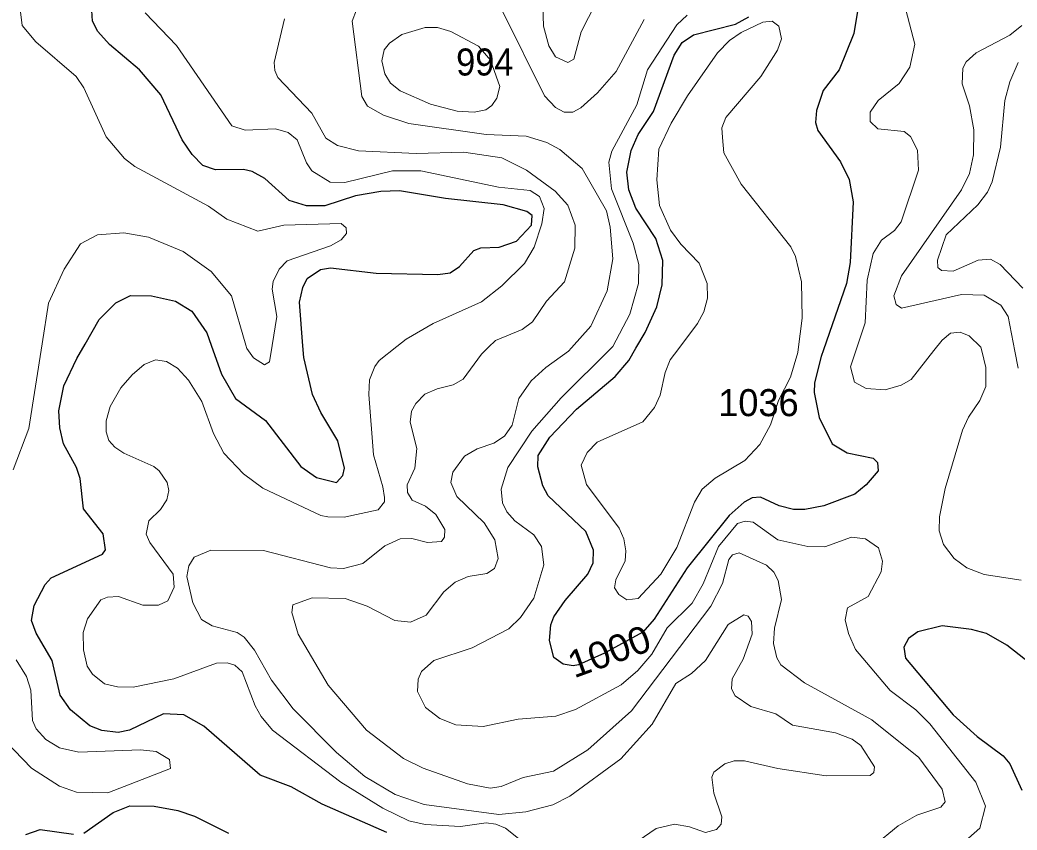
# Model space of a CAD drawing. Extents: x 473.9 to 500, y 7733.1 to 7760.8.
# Drawn here: x 479.198 to 482.147, y 7746.544 to 7748.942 of the extents above; entities that cross this region are included whole.
import ezdxf
from ezdxf.enums import TextEntityAlignment as Align

# ---------------------------------------------------------------- set-up
doc = ezdxf.new("R2010")
doc.units = 0
doc.header["$LTSCALE"] = 0.032
doc.layers.add('1', color=7, linetype='Continuous', lineweight=25)
doc.layers.add('2', color=7, linetype='Continuous', lineweight=13)
doc.layers.add('21', color=7, linetype='Continuous')
doc.layers.add('61', color=7, linetype='Continuous')

msp = doc.modelspace()

# ---------------------------------------------------------------- linework, layer by layer
at = {"layer": '1'}
for points in [[(481.6787, 7748.9918), (481.664, 7748.9011), (481.621, 7748.794), (481.5738, 7748.7331), (481.554, 7748.6734), (481.5507, 7748.6378), (481.5572, 7748.6146), (481.6246, 7748.5216), (481.6499, 7748.4698), (481.6616, 7748.4036), (481.6535, 7748.2242), (481.6423, 7748.1614), (481.5745, 7747.9657), (481.5675, 7747.9454), (481.5479, 7747.8675), (481.5467, 7747.8395), (481.5618, 7747.7649), (481.6003, 7747.6876), (481.6439, 7747.6606), (481.7211, 7747.6443), (481.7341, 7747.6319), (481.7364, 7747.6076), (481.7009, 7747.5655), (481.667, 7747.5385), (481.5754, 7747.5038), (481.5196, 7747.4928), (481.486, 7747.4932), (481.4435, 7747.5036), (481.3876, 7747.5295), (481.3631, 7747.5271), (481.3393, 7747.5142), (481.295, 7747.4749), (481.1707, 7747.3206), (481.0738, 7747.168), (481.0404, 7747.1294), (480.9267, 7747.068), (480.8499, 7747.0326), (480.834, 7747.0303), (480.8044, 7747.035), (480.7766, 7747.0543), (480.7643, 7747.1048), (480.7683, 7747.151), (480.7763, 7747.1747), (480.8099, 7747.223), (480.8775, 7747.3018), (480.8928, 7747.335), (480.8938, 7747.3723), (480.8715, 7747.4277), (480.7605, 7747.5337), (480.7443, 7747.5626), (480.729, 7747.6192), (480.7306, 7747.6521), (480.7646, 7747.707), (480.8441, 7747.7896), (480.9585, 7747.8868), (480.9983, 7747.9342), (481.0196, 7747.9699), (481.0471, 7748.0162), (481.0811, 7748.0924), (481.0972, 7748.1572), (481.0988, 7748.23), (481.0787, 7748.2949), (481.0195, 7748.3847), (480.9988, 7748.4392), (480.9927, 7748.4907), (481.0053, 7748.5552), (481.0263, 7748.6031), (481.0717, 7748.671), (481.1323, 7748.8379), (481.1566, 7748.8745), (481.1894, 7748.8973), (481.3141, 7748.9296), (481.3534, 7748.9505)], [(479.6826, 7746.8849), (479.6222, 7746.8877), (479.5219, 7746.8399), (479.4885, 7746.8325), (479.44, 7746.8387), (479.4041, 7746.8529), (479.347, 7746.8997), (479.3171, 7746.9429), (479.2926, 7747.0459), (479.2458, 7747.1271), (479.232, 7747.1645), (479.2402, 7747.2088), (479.2721, 7747.2706), (479.2903, 7747.2905), (479.4417, 7747.3603), (479.4505, 7747.3731), (479.4435, 7747.421), (479.3861, 7747.4948), (479.376, 7747.5847), (479.3655, 7747.6173), (479.3261, 7747.6875), (479.3155, 7747.7344), (479.3123, 7747.7852), (479.3278, 7747.859), (479.3662, 7747.9398), (479.3908, 7747.9824), (479.4325, 7748.0548), (479.4811, 7748.1042), (479.5243, 7748.126), (479.5872, 7748.1252), (479.6574, 7748.1093), (479.706, 7748.0793), (479.7509, 7748.0159), (479.7636, 7747.9796), (479.7939, 7747.893), (479.8353, 7747.8217), (479.9236, 7747.7558), (480.0283, 7747.6204), (480.0751, 7747.5879), (480.1338, 7747.5722), (480.1523, 7747.5938), (480.1579, 7747.615), (480.1381, 7747.6956), (480.0877, 7747.7799), (480.0632, 7747.8329), (480.0374, 7747.9425), (480.0347, 7747.9775), (480.0247, 7748.1068), (480.0343, 7748.15), (480.0476, 7748.1769), (480.0869, 7748.2029), (480.1163, 7748.208), (480.2512, 7748.1924), (480.4336, 7748.1887), (480.4697, 7748.1936), (480.4978, 7748.2118), (480.5399, 7748.2589), (480.561, 7748.2675), (480.6154, 7748.2688), (480.6659, 7748.2865), (480.7103, 7748.334), (480.7123, 7748.3631), (480.6969, 7748.3747), (480.627, 7748.3943), (480.4559, 7748.4131), (480.3199, 7748.4357), (480.2649, 7748.4341), (480.1899, 7748.4206), (480.0996, 7748.3914), (480.045, 7748.3918), (479.9942, 7748.4075), (479.9223, 7748.4722), (479.8849, 7748.4929), (479.859, 7748.4993), (479.776, 7748.4982), (479.7391, 7748.511), (479.7069, 7748.5438), (479.6779, 7748.5869), (479.6141, 7748.7205), (479.5513, 7748.7939), (479.4623, 7748.8694), (479.4277, 7748.9071), (479.4122, 7748.9377), (479.4104, 7748.9696)], [(482.2035, 7747.0234), (482.117, 7747.0917), (482.0562, 7747.1256), (482.0122, 7747.1379), (481.9253, 7747.1483), (481.8531, 7747.1307), (481.8253, 7747.1105), (481.8115, 7747.085), (481.8168, 7747.0528), (481.958, 7746.8851), (482.0288, 7746.8212), (482.106, 7746.7633), (482.1257, 7746.7401), (482.1612, 7746.6623)], [(480.283, 7746.5365), (480.0912, 7746.6207), (480.0003, 7746.6718), (479.9087, 7746.7065), (479.742, 7746.8516), (479.6826, 7746.8849)], [(479.3865, 7746.5349), (479.4739, 7746.596), (479.523, 7746.6153), (479.5944, 7746.6145), (479.6644, 7746.6024), (479.7143, 7746.5855), (479.8146, 7746.5346)], [(479.215, 7746.5311), (479.2577, 7746.546), (479.356, 7746.5314)]]:
    msp.add_lwpolyline(points, dxfattribs=at)
at = {"layer": '2'}
for points in [[(479.9571, 7748.0638), (479.9435, 7748.1448), (479.9467, 7748.1679), (479.9649, 7748.2041), (479.9882, 7748.2284), (480.1167, 7748.2735), (480.1482, 7748.291), (480.1636, 7748.31), (480.1626, 7748.3261), (480.1475, 7748.339), (479.978, 7748.3343), (479.9016, 7748.3167), (479.8101, 7748.3523), (479.7555, 7748.3907), (479.5377, 7748.5084), (479.5072, 7748.5318), (479.4524, 7748.596), (479.387, 7748.7403), (479.3641, 7748.7744), (479.2451, 7748.8766), (479.2046, 7748.9254), (479.1918, 7749.0303), (479.1979, 7749.1483), (479.166, 7749.3096)], [(480.7431, 7749.0143), (480.746, 7748.9231), (480.7618, 7748.8648), (480.7813, 7748.8323), (480.8185, 7748.8153), (480.8361, 7748.8258), (480.858, 7748.9066), (480.9661, 7749.1191)], [(479.568, 7748.9631), (479.6605, 7748.8659), (479.8245, 7748.6287), (479.8639, 7748.6158), (479.9532, 7748.619), (479.991, 7748.6086), (480.0175, 7748.5869), (480.0448, 7748.5185), (480.0609, 7748.4952), (480.1148, 7748.4614), (480.1582, 7748.4606), (480.2997, 7748.4952), (480.3833, 7748.4952), (480.6133, 7748.447), (480.7065, 7748.4373), (480.7339, 7748.4196), (480.7483, 7748.3834), (480.7411, 7748.3384), (480.7186, 7748.2693), (480.6904, 7748.221), (480.6229, 7748.1551), (480.5626, 7748.1077), (480.4203, 7748.0433), (480.3399, 7747.9967), (480.3128, 7747.9754), (480.2603, 7747.934), (480.2474, 7747.9163), (480.2313, 7747.8769), (480.2297, 7747.8335), (480.2434, 7747.655), (480.2715, 7747.5601), (480.2756, 7747.528), (480.2756, 7747.5159), (480.2571, 7747.4918), (480.1566, 7747.4701), (480.1083, 7747.4709), (480.0874, 7747.4749), (479.9162, 7747.5561), (479.8591, 7747.5987), (479.8012, 7747.6598), (479.7698, 7747.7177), (479.7361, 7747.8126), (479.6959, 7747.8753), (479.6637, 7747.9115), (479.6316, 7747.9308), (479.5986, 7747.9356), (479.5648, 7747.9219), (479.5294, 7747.8914), (479.4965, 7747.8528), (479.4643, 7747.7973), (479.4523, 7747.7547), (479.4523, 7747.7225), (479.4611, 7747.6968), (479.478, 7747.6775), (479.5053, 7747.659), (479.5938, 7747.6204), (479.6098, 7747.6076), (479.6332, 7747.573), (479.638, 7747.5489), (479.6323, 7747.5215), (479.6131, 7747.4926), (479.5785, 7747.4588), (479.5713, 7747.4202), (479.5817, 7747.3953), (479.6508, 7747.3012), (479.6541, 7747.2626), (479.6348, 7747.2224), (479.6074, 7747.2096), (479.5616, 7747.2096), (479.4892, 7747.2353), (479.4571, 7747.2337), (479.437, 7747.2257), (479.3976, 7747.1694), (479.3847, 7747.1292), (479.3855, 7747.0777), (479.3968, 7747.0295), (479.4121, 7747.0053), (479.4474, 7746.9772), (479.486, 7746.9684), (479.5327, 7746.9668), (479.6533, 7746.9917), (479.7787, 7747.0383), (479.8109, 7747.0391), (479.8334, 7747.0319), (479.8551, 7747.0126), (479.8937, 7746.9121), (479.9113, 7746.8799)], [(480.3657, 7747.6152), (480.372, 7747.6734), (480.3517, 7747.7509), (480.3559, 7747.784), (480.3683, 7747.8066), (480.3948, 7747.8341), (480.4315, 7747.8503), (480.4792, 7747.8613), (480.5082, 7747.8789), (480.5629, 7747.9522), (480.5839, 7747.9733), (480.6038, 7747.9933), (480.683, 7748.025), (480.7141, 7748.0485), (480.7555, 7748.1093), (480.8085, 7748.1664), (480.839, 7748.2659), (480.84, 7748.3347), (480.8181, 7748.393), (480.7812, 7748.4348), (480.696, 7748.4967), (480.6233, 7748.5336), (480.5108, 7748.5507), (480.3698, 7748.5466), (480.1994, 7748.5545), (480.1366, 7748.5696), (480.1028, 7748.592), (480.0609, 7748.6657), (479.9606, 7748.7718), (479.9513, 7748.7924), (479.9499, 7748.8159), (479.9804, 7748.9451)], [(480.1932, 7748.9715), (480.1799, 7748.9376), (480.2094, 7748.7152), (480.2257, 7748.686), (480.2729, 7748.6596), (480.3477, 7748.6354), (480.5762, 7748.6029), (480.6947, 7748.598), (480.7562, 7748.5788), (480.7949, 7748.5578), (480.8609, 7748.5018), (480.9329, 7748.3765), (480.9436, 7748.3287), (480.9516, 7748.2349), (480.9342, 7748.1395), (480.8861, 7748.0349), (480.8292, 7747.9714), (480.8202, 7747.9614), (480.7528, 7747.9133), (480.7101, 7747.8731), (480.6731, 7747.8211), (480.6535, 7747.7422), (480.6312, 7747.7101), (480.5993, 7747.6891), (480.5499, 7747.6723), (480.5126, 7747.6511), (480.4776, 7747.6035), (480.4726, 7747.5724), (480.4899, 7747.5316), (480.571, 7747.4535), (480.6025, 7747.4029), (480.6124, 7747.3476), (480.6008, 7747.3177), (480.5789, 7747.3034), (480.5232, 7747.2943), (480.485, 7747.2781), (480.451, 7747.2494), (480.3988, 7747.1796), (480.3533, 7747.159), (480.307, 7747.1641), (480.225, 7747.2064), (480.1594, 7747.2297), (480.0618, 7747.2311), (480.0052, 7747.2105), (480.0014, 7747.188), (480.0211, 7747.1236), (480.1094, 7746.9727), (480.2229, 7746.8401), (480.332, 7746.7554), (480.3901, 7746.7272), (480.5215, 7746.6813), (480.588, 7746.6677), (480.6212, 7746.6733)], [(481.0444, 7748.943), (480.9609, 7748.7891), (480.9057, 7748.7257), (480.8568, 7748.6817), (480.833, 7748.6686), (480.8078, 7748.6689), (480.7817, 7748.6828), (480.7489, 7748.7173), (480.6236, 7748.97)], [(480.9463, 7747.9705), (480.9508, 7747.975), (481.0019, 7748.0709), (481.0272, 7748.1614), (481.028, 7748.2177), (481.0115, 7748.281), (480.9475, 7748.4418), (480.9397, 7748.5211), (480.9481, 7748.5528), (481.0222, 7748.69), (481.0535, 7748.7944), (481.1407, 7748.9269), (481.1708, 7748.9556)], [(481.8183, 7748.9718), (481.8442, 7748.8695), (481.8296, 7748.8015), (481.798, 7748.7539), (481.7357, 7748.7033), (481.7124, 7748.6686), (481.7128, 7748.6408), (481.7346, 7748.6193), (481.8127, 7748.6117), (481.8312, 7748.5964), (481.852, 7748.5559), (481.8554, 7748.497), (481.8036, 7748.3443), (481.7844, 7748.3189), (481.7459, 7748.2897), (481.7216, 7748.2505), (481.7036, 7748.1717), (481.6977, 7748.0456), (481.671, 7747.9649), (481.6545, 7747.9149), (481.6659, 7747.8694), (481.7003, 7747.8505), (481.757, 7747.8465), (481.8042, 7747.8606), (481.8332, 7747.8779), (481.9006, 7747.9632), (481.9249, 7747.994), (481.95, 7748.0151), (481.9782, 7748.0175), (482.0052, 7748.0064), (482.0395, 7747.9731), (482.0423, 7747.9621), (482.0549, 7747.9133), (482.0541, 7747.8565), (482.0371, 7747.8158), (482.0036, 7747.7665), (481.9857, 7747.7273), (481.9338, 7747.5547), (481.9174, 7747.4711), (481.9167, 7747.4293), (481.9294, 7747.3893), (481.9608, 7747.3479), (481.9983, 7747.3202), (482.0497, 7747.3002), (482.1591, 7747.2832)], [(482.15, 7747.9114), (482.1402, 7747.9613), (482.1202, 7748.064), (482.099, 7748.0971), (482.0499, 7748.1269), (481.9822, 7748.1293), (481.8053, 7748.0884), (481.7889, 7748.0993), (481.7822, 7748.1255), (481.8052, 7748.1841), (481.9826, 7748.4386), (482.0059, 7748.4868), (482.0178, 7748.5425), (482.0194, 7748.6163), (482.0064, 7748.6878), (481.984, 7748.7522), (481.9868, 7748.7988), (481.9965, 7748.8173), (482.0255, 7748.8444), (482.1257, 7748.897), (482.1608, 7748.9253)], [(482.1499, 7748.816), (482.1252, 7748.7586), (482.1111, 7748.7028), (482.0974, 7748.5652), (482.0736, 7748.4628), (482.0596, 7748.4316), (482.0311, 7748.3943), (481.9373, 7748.3055), (481.9114, 7748.2308), (481.9123, 7748.2091), (481.9232, 7748.2006), (481.9577, 7748.1984), (482.0314, 7748.2306), (482.0681, 7748.2333), (482.0972, 7748.2174), (482.1634, 7748.1481)], [(479.1779, 7747.6105), (479.2238, 7747.7322), (479.2632, 7747.9834), (479.282, 7748.103), (479.3281, 7748.2043), (479.3771, 7748.2792), (479.4272, 7748.3055), (479.5052, 7748.3117), (479.5776, 7748.2989), (479.6808, 7748.2565), (479.7634, 7748.1974), (479.8233, 7748.1247), (479.8656, 7747.9788), (479.8684, 7747.9691), (479.8885, 7747.9414), (479.9208, 7747.921), (479.9363, 7747.9299), (479.9438, 7747.9782), (479.9571, 7748.0638)], [(481.9863, 7746.5053), (482.0367, 7746.5492), (482.053, 7746.6145), (482.0247, 7746.6858), (481.8887, 7746.8586), (481.8474, 7746.8999), (481.7713, 7746.9567), (481.6691, 7747.0786), (481.6482, 7747.1254), (481.6384, 7747.1661), (481.6456, 7747.2018), (481.7061, 7747.2357), (481.7446, 7747.3081), (481.7492, 7747.3397), (481.737, 7747.3792), (481.6986, 7747.4059), (481.6568, 7747.4105), (481.5785, 7747.3821), (481.5281, 7747.3832), (481.4389, 7747.4027), (481.3668, 7747.4548), (481.3427, 7747.4579), (481.3196, 7747.451), (481.2639, 7747.3833), (481.2187, 7747.2727), (481.1856, 7747.2152), (481.1118, 7747.1427), (481.0665, 7747.0649), (481.0256, 7747.0165), (480.9755, 7746.9734), (480.8409, 7746.9012), (480.7831, 7746.8814), (480.6717, 7746.8718), (480.5676, 7746.851), (480.4867, 7746.8552), (480.4398, 7746.8742), (480.3971, 7746.9064), (480.3731, 7746.9544), (480.3757, 7746.9903), (480.3852, 7747.0131), (480.4219, 7747.0454), (480.5354, 7747.0829), (480.6441, 7747.1392), (480.6779, 7747.1729), (480.7178, 7747.2305), (480.7474, 7747.3291), (480.74, 7747.3837), (480.7181, 7747.4173), (480.6615, 7747.4588), (480.6382, 7747.4854), (480.625, 7747.5129), (480.6206, 7747.5525), (480.6403, 7747.6173), (480.7118, 7747.7243), (480.7982, 7747.8237), (480.9463, 7747.9705)], [(481.026, 7746.512), (481.0794, 7746.5486), (481.134, 7746.5615), (481.178, 7746.554), (481.2258, 7746.5366), (481.2575, 7746.5454), (481.272, 7746.5618), (481.2732, 7746.5836), (481.2499, 7746.6529), (481.2444, 7746.7008), (481.25, 7746.7152), (481.2828, 7746.7403), (481.3104, 7746.749), (481.3407, 7746.749), (481.4388, 7746.7259), (481.5823, 7746.7047), (481.7122, 7746.7053), (481.7231, 7746.7143), (481.7253, 7746.731), (481.6849, 7746.7946), (481.6591, 7746.8128), (481.61, 7746.8313), (481.4827, 7746.8545), (481.4334, 7746.8879), (481.3595, 7746.9097), (481.3126, 7746.941), (481.302, 7746.9617), (481.3041, 7746.9917), (481.3372, 7747.0494), (481.3635, 7747.1236), (481.3617, 7747.1614), (481.352, 7747.1773), (481.3387, 7747.1811), (481.2921, 7747.152), (481.2253, 7747.046), (481.1844, 7747.0073), (481.1373, 7746.9777), (481.0678, 7746.8578), (480.975, 7746.7545), (480.8237, 7746.6444), (480.7735, 7746.6191), (480.6937, 7746.598), (480.6137, 7746.5897), (480.3934, 7746.6197), (480.3071, 7746.6494), (480.2181, 7746.7026), (480.1339, 7746.7738), (480.0062, 7746.9032), (479.9421, 7746.9877), (479.8919, 7747.076), (479.8606, 7747.1146), (479.8398, 7747.1291), (479.7658, 7747.1486), (479.7348, 7747.1668), (479.7091, 7747.217), (479.6911, 7747.2945), (479.6972, 7747.3259), (479.7128, 7747.3517), (479.7625, 7747.3727), (479.9179, 7747.3712), (480.1162, 7747.32), (480.1549, 7747.3181), (480.2123, 7747.3331), (480.2765, 7747.3854), (480.3221, 7747.4057), (480.3564, 7747.4065), (480.4031, 7747.3953), (480.445, 7747.3983), (480.4531, 7747.4105), (480.4543, 7747.4337), (480.4282, 7747.478), (480.3971, 7747.503), (480.3578, 7747.5201), (480.3438, 7747.5434), (480.343, 7747.566), (480.3657, 7747.6152)], [(480.6212, 7746.6733), (480.6861, 7746.6998), (480.7762, 7746.718), (480.877, 7746.7816), (481.0069, 7746.8971), (481.2407, 7747.2068), (481.2759, 7747.2741), (481.2945, 7747.3452), (481.3051, 7747.3588), (481.3245, 7747.3644), (481.4058, 7747.3283), (481.4276, 7747.3077), (481.4407, 7747.283), (481.4501, 7747.2267), (481.429, 7747.1414), (481.4261, 7747.0959), (481.4359, 7747.0536), (481.4486, 7747.0332), (481.5183, 7746.9795), (481.7168, 7746.8699), (481.8563, 7746.759), (481.925, 7746.665), (481.9342, 7746.6276), (481.921, 7746.6119), (481.8508, 7746.5877), (481.7956, 7746.5569), (481.7233, 7746.4974)], [(479.1555, 7746.8067), (479.2316, 7746.7276), (479.3149, 7746.6743), (479.3654, 7746.6564), (479.4581, 7746.6546), (479.6427, 7746.7259), (479.6402, 7746.753), (479.6006, 7746.7768), (479.5546, 7746.7818), (479.3723, 7746.7741), (479.3144, 7746.7875), (479.2743, 7746.8116), (479.2459, 7746.8441), (479.2344, 7746.8687), (479.2295, 7746.9581), (479.2174, 7746.9988), (479.1864, 7747.0476)], [(479.9113, 7746.8799), (479.9443, 7746.8397), (480.1469, 7746.6862), (480.2708, 7746.609), (480.3479, 7746.5712), (480.3962, 7746.5607), (480.5007, 7746.5543), (480.5763, 7746.5656), (480.6052, 7746.5615), (480.6342, 7746.5495), (480.721, 7746.4803)]]:
    msp.add_lwpolyline(points, dxfattribs=at)
for points in [[(480.3225, 7748.732), (480.2938, 7748.7547), (480.2767, 7748.7818), (480.2682, 7748.8202), (480.2752, 7748.8535), (480.2906, 7748.8727), (480.3275, 7748.8989), (480.3967, 7748.9196), (480.4331, 7748.9196), (480.4723, 7748.9079), (480.5537, 7748.8641), (480.5898, 7748.8224), (480.6171, 7748.7451), (480.6084, 7748.7099), (480.5935, 7748.6886), (480.5752, 7748.6759), (480.5408, 7748.6689), (480.491, 7748.6713), (480.4117, 7748.6927)], [(481.0744, 7747.7942), (481.0916, 7747.8308), (481.1062, 7747.8983), (481.1212, 7747.9358), (481.1462, 7747.969), (481.202, 7748.0429), (481.2206, 7748.0773), (481.2315, 7748.1179), (481.2299, 7748.1618), (481.2067, 7748.222), (481.1527, 7748.2779), (481.1218, 7748.3195), (481.0895, 7748.3925), (481.0811, 7748.4683), (481.0877, 7748.5592), (481.1238, 7748.6358), (481.1721, 7748.7168), (481.2605, 7748.8442), (481.2966, 7748.881), (481.3308, 7748.9046), (481.3948, 7748.9349), (481.4225, 7748.9381), (481.4422, 7748.9229), (481.4501, 7748.886), (481.4387, 7748.8524), (481.3894, 7748.7746), (481.2851, 7748.653), (481.2737, 7748.622), (481.2752, 7748.5941), (481.2796, 7748.5484), (481.3304, 7748.4558), (481.4776, 7748.2702), (481.4911, 7748.2419), (481.5095, 7748.1669), (481.5112, 7748.0586), (481.4998, 7747.9663), (481.4987, 7747.9573), (481.4765, 7747.8844), (481.4412, 7747.8152), (481.4172, 7747.7433), (481.3863, 7747.685), (481.3415, 7747.638), (481.2537, 7747.5853), (481.2154, 7747.5527), (481.1926, 7747.5145), (481.1406, 7747.38), (481.0936, 7747.3012), (481.0265, 7747.2298), (480.9929, 7747.2254), (480.9694, 7747.2409), (480.956, 7747.2611), (480.9599, 7747.285), (480.9877, 7747.3413), (480.9902, 7747.3709), (480.9841, 7747.4062), (480.9698, 7747.4378), (480.8729, 7747.5666), (480.8577, 7747.6239), (480.8757, 7747.6618), (480.9049, 7747.692), (481.0403, 7747.7521)]]:
    msp.add_lwpolyline(points, close=True, dxfattribs=at)

# ---------------------------------------------------------------- texts
at = {"layer": '21', "width": 0.95}
msp.add_text('994', height=0.08, dxfattribs=at).set_placement((480.4878, 7748.7772))
at = {"layer": '21'}
msp.add_text('1036', height=0.08, dxfattribs=at).set_placement((481.2629, 7747.769))
at = {"layer": '61', "width": 1.05}
msp.add_text('1000', height=0.08, rotation=19.916, dxfattribs=at).set_placement((480.954, 7747.0353), align=Align.CENTER)

doc.saveas('drawing.dxf')
